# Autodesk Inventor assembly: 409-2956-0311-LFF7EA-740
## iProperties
Created: 2010-09
Part Number: 409-2956-0311-LFF7EA-740
Document SubType Name: Weldment
Designer: S. Boerckel
Weld Material: Welded Steel Mild
Mass: 52503.1 g
Surface Area: 19694.8 cm^2
Volume: 6663.5 cm^3
Density: 7.87922 g/cm^3
Description: DISCHARGE SPOOL
Material: WELDMENT
SMR: =<MATERIAL>
Author: S. Boerckel
Revision Number: B
